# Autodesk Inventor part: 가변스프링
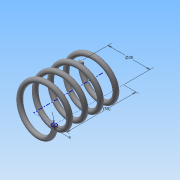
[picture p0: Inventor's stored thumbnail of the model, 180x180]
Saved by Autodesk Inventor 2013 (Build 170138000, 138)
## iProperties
Created: 2015-03
Part Number: 가변스프링
Material: 강철, 탄소
Document SubType Name: Modeling
Designer: Administrator
Density: 7.87 g/cm^3
Mass: 48.2733 g
Surface Area: 62.0009 cm^2
Volume: 6.13383 cm^3
Author: Administrator
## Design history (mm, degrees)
sketch "스케치1"
  geometry: L1 (0, 0)-(17.5, 0); L2 (17.5, 0)-(17.5, 43.5); L3 (17.5, 43.5)-(0, 43.5); L4 (0, 43.5)-(0, 0); C1 r 2 at (17.5, 0)
  constraints: 8 end point, 2 parallel, 1 centre point, 1 coincident, 1 horizontal, 1 perpendicular
  dimensions: "d0" = 35 diameter of L2 L4; "d2" = 43.5 distance of L1.end L2.end (derived); "d3" = 4 diameter of C1
feature "코일1" sketch "스케치1" pitch "d4" = 10; turns "d6" = 4.5; dims "d5" = 43.5 (= d2), "d7" = 0, angle "d8" = 90 deg, angle "d9" = 90 deg, "d10" = 0, "d11" = 0
node "작업 평면1"
sketch "스케치2"
  geometry: L1 (-19.5, 0)-(-15.5, 0) reference; 1 further point
  constraints: 1 horizontal alignment
extrude "돌출1" cut sketch "스케치2" stored distance "d13" = 10; taper "d14" = 0 deg
node "작업 평면2"
sketch "스케치3"
  geometry: L1 (-19.5, 0)-(-15.5, 0) reference; 1 further point
  constraints: 1 horizontal alignment
extrude "돌출2" cut sketch "스케치3" stored distance "d16" = 10; taper "d17" = 0 deg
node "솔리드1"
node "절단 모서리 투영1"
node "절단 모서리 투영2"
other parameters: "d12" = 0, "d15" = -43.5 (= -d2)
